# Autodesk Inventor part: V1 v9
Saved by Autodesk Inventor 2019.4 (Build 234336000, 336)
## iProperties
Created: 2020-01
Part Number: V1 v9
Material: Generic
Document SubType Name: Modeling
Designer: Administrator
Density: 1 g/cm^3
Appearance: Default
Author: Administrator
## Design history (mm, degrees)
feature "Body2"
feature "Body10"
body "Solid1"
body "Solid2"
